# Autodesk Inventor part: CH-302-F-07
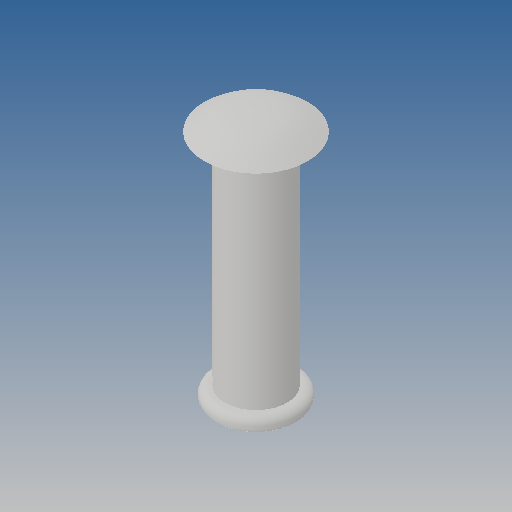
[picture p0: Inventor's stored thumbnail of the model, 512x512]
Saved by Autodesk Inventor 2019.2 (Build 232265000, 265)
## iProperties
Created: 2013-03
Part Number: CH-302-F-07
Material: Ogólny
Document SubType Name: Modeling
Designer: CADENGINEERING4
Density: 1 g/cm^3
Appearance: Domyślna
Author: CADENGINEERING4
Revision Number: ÈÎºÎ
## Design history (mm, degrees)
feature "Ô²½Ç2"
node "Bryła1"
